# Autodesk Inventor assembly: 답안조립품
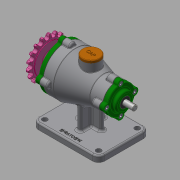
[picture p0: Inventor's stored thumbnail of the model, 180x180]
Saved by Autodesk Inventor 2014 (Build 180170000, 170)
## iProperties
Created: 2020-12
Part Number: 답안조립품
Document SubType Name: Assembly
Designer: kh
Author: kh
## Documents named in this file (15)
- C:\Users\kh\Desktop\701206V1030\답안조립품.iam
- C:\Users\kh\Desktop\701206V1030\본체.ipt
- C:\Users\kh\Desktop\701206V1030\개스킷 A.ipt
- C:\Users\kh\Desktop\701206V1030\개스킷 B.ipt
- C:\Users\kh\Desktop\701206V1030\앞커버.ipt
- C:\Users\kh\Desktop\701206V1030\뒤커버.ipt
- C:\Users\kh\Desktop\701206V1030\오일 실 17 30 8.ipt
- C:\Users\kh\Desktop\701206V1030\오일 실 10 20 7.ipt
- C:\Users\kh\Desktop\701206V1030\베어링 6203.ipt
- C:\Users\kh\Desktop\701206V1030\베어링 6200.ipt
- C:\Users\kh\Desktop\701206V1030\축.ipt
- C:\Users\kh\Desktop\701206V1030\키 4x4x14.ipt
- C:\Users\kh\Desktop\701206V1030\스프로킷.ipt
- C:\Users\kh\Desktop\701206V1030\마개.ipt
- C:\Users\kh\Desktop\701206V1030\볼트 M5.ipt
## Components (2 placed, 2 different names)
1. 개스킷 A:1
2. 개스킷 B:1
